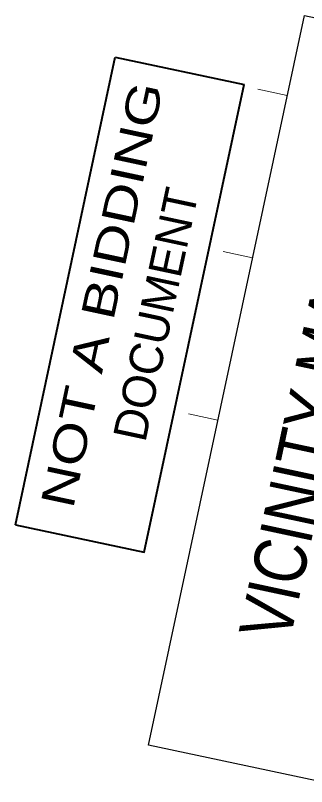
# Model space of a CAD drawing. Extents: x 2363411 to 2369126, y 6976878 to 6988319.
# Drawn here: x 2365480.8 to 2365656.3, y 6976974.9 to 6977439.3 of the extents above; entities that cross this region are included whole.
import ezdxf
from ezdxf.enums import TextEntityAlignment as Align

# ---------------------------------------------------------------- set-up
doc = ezdxf.new("R2010")
doc.units = 0
doc.header["$LTSCALE"] = 2
for name, color, linetype, lineweight in [('40', 7, 'Continuous', 13), ('62', 7, 'Continuous', 13), ('63', 7, 'Continuous', 13)]:
    doc.layers.add(name, color=color, linetype=linetype, lineweight=lineweight)

msp = doc.modelspace()

# ---------------------------------------------------------------- linework, layer by layer
at = {"layer": '40'}
for p, q in [((2365626.917, 6977394.927), (2365644.636, 6977391.141)), ((2365606.02, 6977297.13), (2365623.74, 6977293.344)), ((2365585.124, 6977199.333), (2365602.845, 6977195.547))]:
    msp.add_line(p, q, dxfattribs=at)
at = {"layer": '62', "lineweight": 40}
for p, q in [((2365480.769, 6977132.627), (2365540.942, 6977414.246)), ((2365540.942, 6977414.246), (2365618.63, 6977397.646))]:
    msp.add_line(p, q, dxfattribs=at)
at = {"layer": '62', "lineweight": 25}
msp.add_lwpolyline([(2365678.211, 6976974.92), (2365561.054, 6976999.954), (2365654.924, 6977439.292), (2365772.152, 6977414.588)], dxfattribs=at)
at = {"layer": '62', "lineweight": 40}
msp.add_lwpolyline([(2365480.769, 6977132.627), (2365558.456, 6977116.027), (2365618.63, 6977397.646)], dxfattribs=at)
at = {"layer": '63', "lineweight": 40}
for p, q in [((2365480.769, 6977132.627), (2365540.942, 6977414.246)), ((2365540.942, 6977414.246), (2365618.63, 6977397.646))]:
    msp.add_line(p, q, dxfattribs=at)
at = {"layer": '63'}
for p, q in [((2365626.917, 6977394.927), (2365644.636, 6977391.141)), ((2365606.02, 6977297.13), (2365623.74, 6977293.344)), ((2365585.124, 6977199.333), (2365602.845, 6977195.547))]:
    msp.add_line(p, q, dxfattribs=at)
at = {"layer": '63', "lineweight": 25}
msp.add_lwpolyline([(2365678.211, 6976974.92), (2365561.054, 6976999.954), (2365654.924, 6977439.292), (2365772.152, 6977414.588)], dxfattribs=at)
at = {"layer": '63', "lineweight": 40}
msp.add_lwpolyline([(2365480.769, 6977132.627), (2365558.456, 6977116.027), (2365618.63, 6977397.646)], dxfattribs=at)

# ---------------------------------------------------------------- texts
at = {"layer": '62', "width": 1.3}
msp.add_text('NOT A BIDDING', height=20, rotation=77.939, dxfattribs=at).set_placement((2365542.723, 6977269.113), align=Align.CENTER)
at = {"layer": '62'}
msp.add_text('DOCUMENT', height=20, rotation=77.939, dxfattribs=at).set_placement((2365575.155, 6977257.214), align=Align.CENTER)
at = {"layer": '62', "width": 0.85}
msp.add_text('VICINITY MAP', height=31.45, rotation=77.939, dxfattribs=at).set_placement((2365646.069, 6977061.634))
at = {"layer": '63', "width": 1.3}
msp.add_text('NOT A BIDDING', height=20, rotation=77.939, dxfattribs=at).set_placement((2365542.723, 6977269.113), align=Align.CENTER)
at = {"layer": '63'}
msp.add_text('DOCUMENT', height=20, rotation=77.939, dxfattribs=at).set_placement((2365575.155, 6977257.214), align=Align.CENTER)
at = {"layer": '63', "width": 0.85}
msp.add_text('VICINITY MAP', height=31.45, rotation=77.939, dxfattribs=at).set_placement((2365646.069, 6977061.634))

doc.saveas('drawing.dxf')
